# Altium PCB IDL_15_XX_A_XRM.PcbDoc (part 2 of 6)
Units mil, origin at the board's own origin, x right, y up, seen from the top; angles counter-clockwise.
Board outline 6653.34 x 6653.34 mil, 6 copper layers (Top Layer - SIG1, Layer 2 - GND1, Layer 3 - PWR, Layer 4 - PWR, Layer 5 - GND2, Bottom Layer - SIG4), stack 59.843 mil thick; 613 components, 324 nets, 1673 pads, 2316 vias.
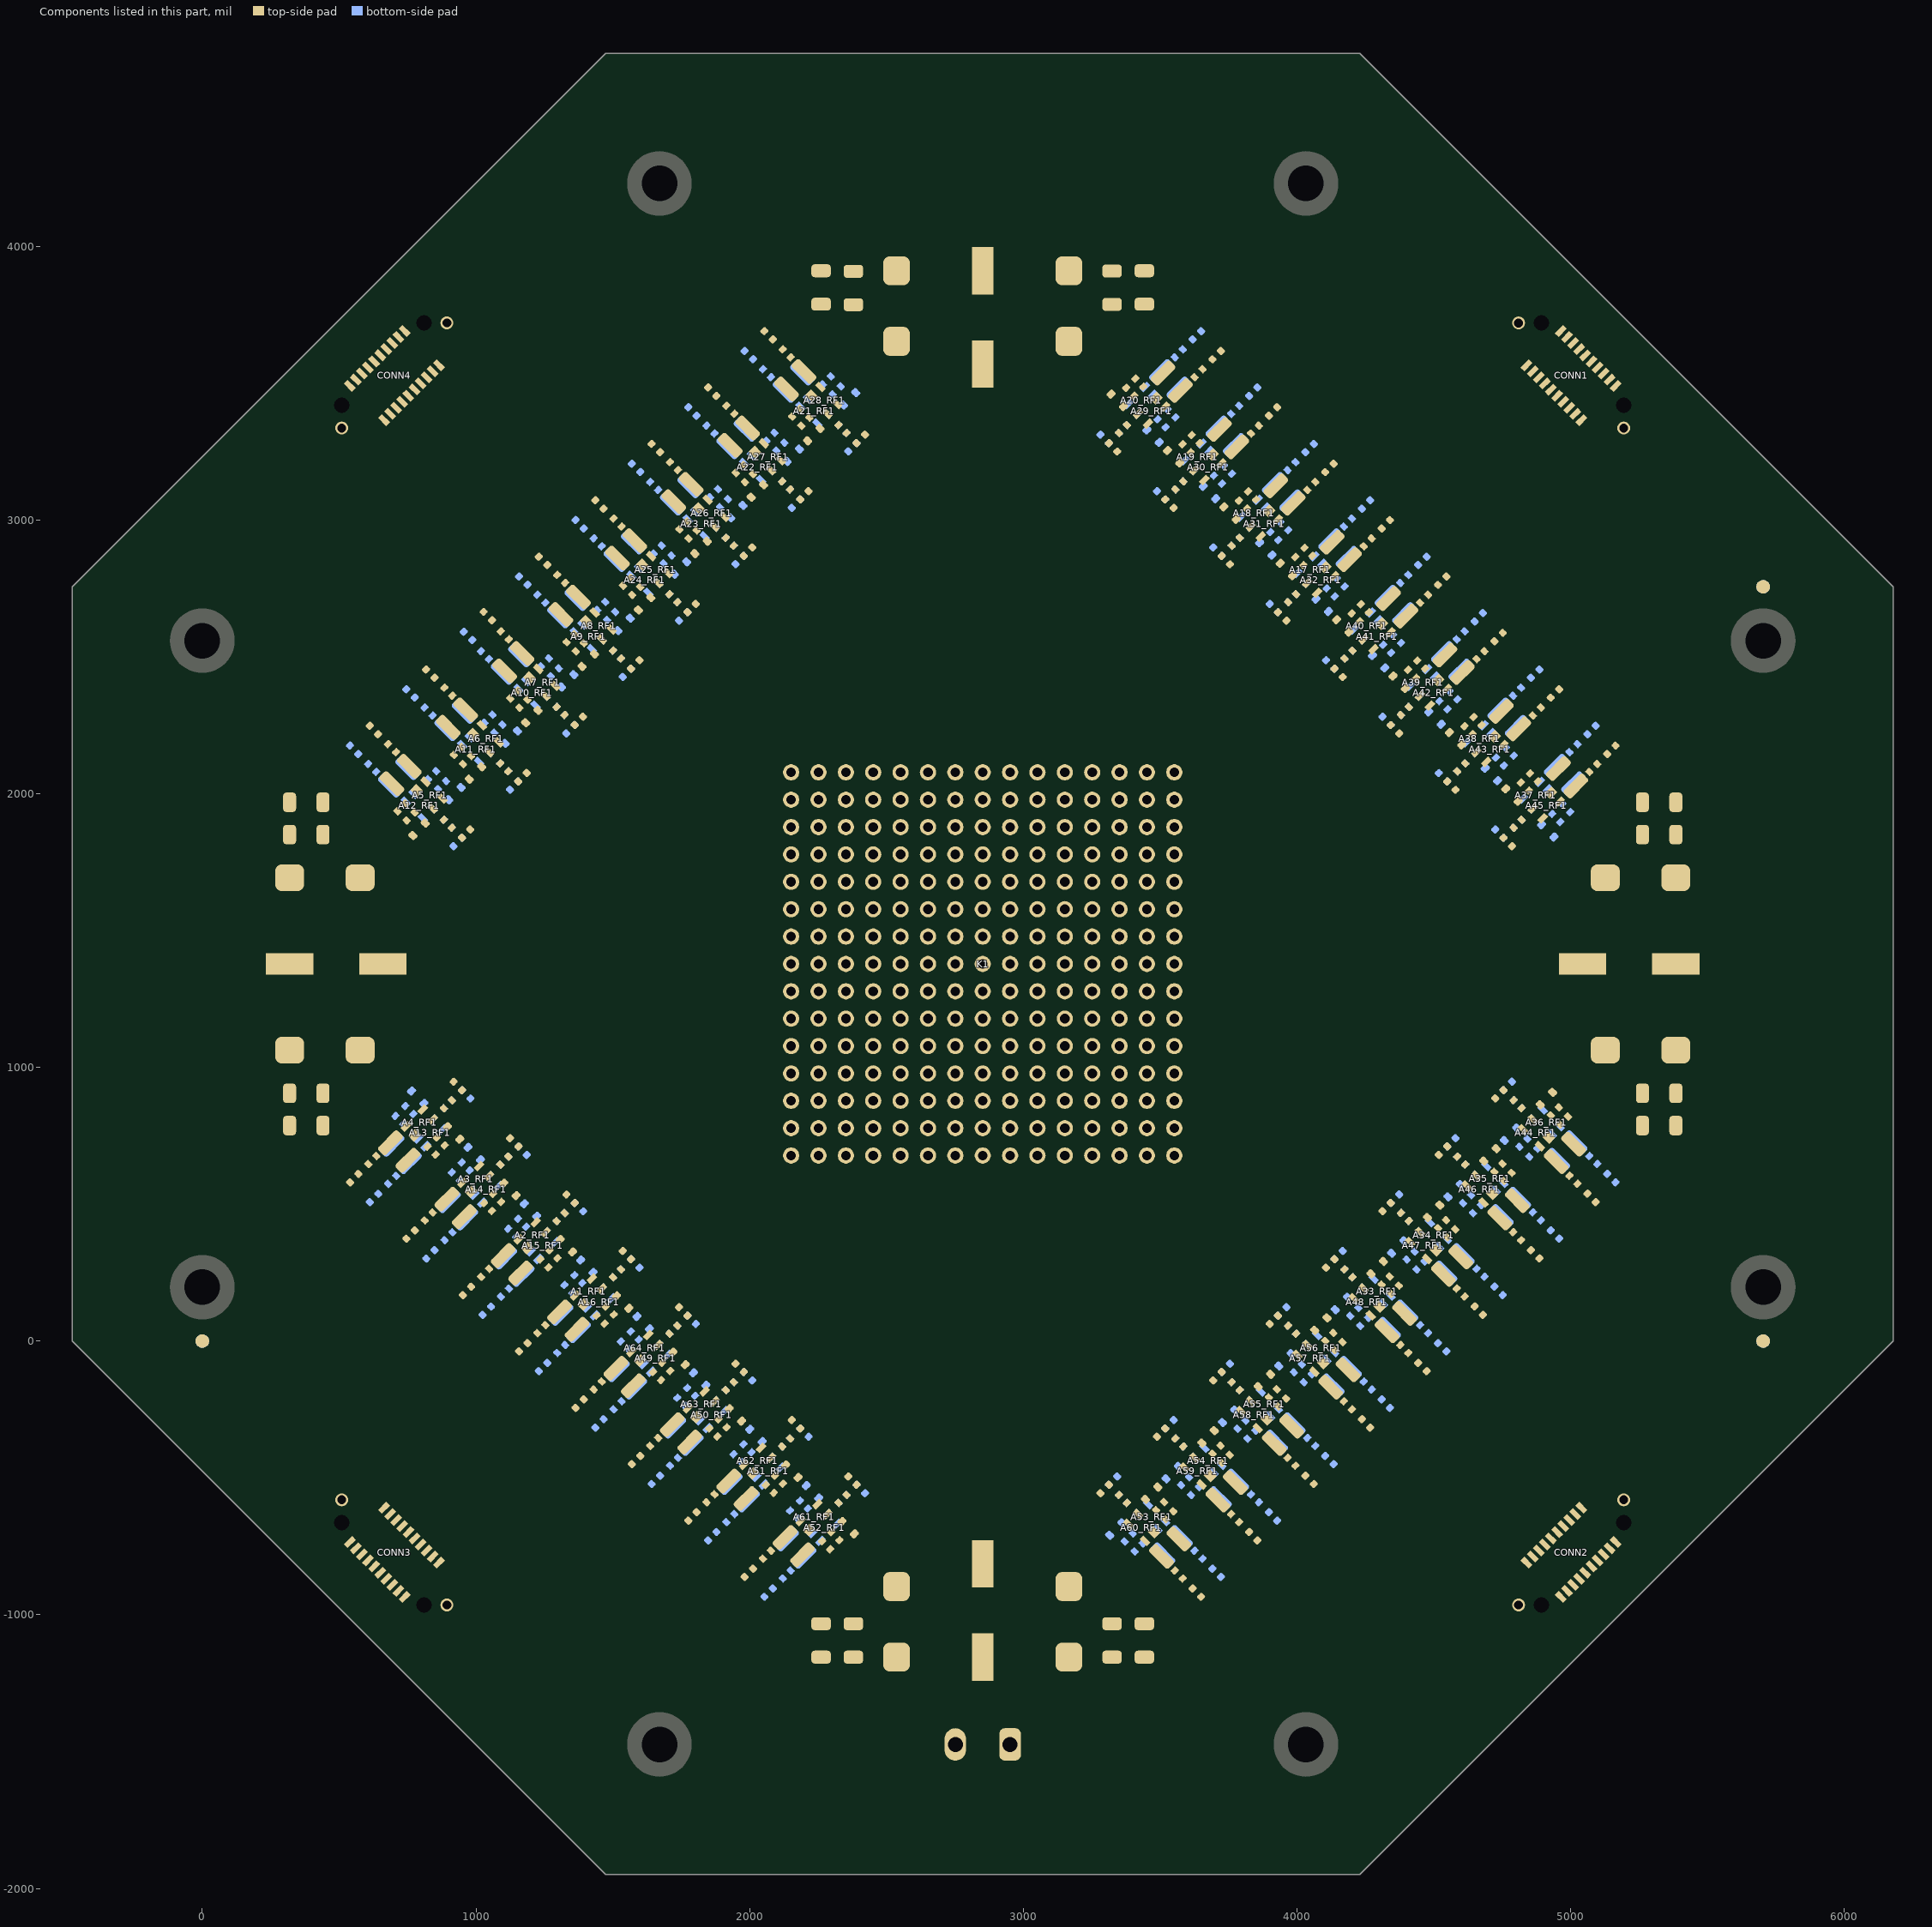
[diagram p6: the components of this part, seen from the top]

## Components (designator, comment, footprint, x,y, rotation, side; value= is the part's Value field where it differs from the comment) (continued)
A28_Cin_1 "10nF" CC0402N1R 2339.1,3332.37 r135 top (schematic designator Cin_1)
A28_L1 "1.5uH" LC1008CS 2166.5,3510.54 r225 top (schematic designator L1)
A28_L2 "0.5nH" LC0402N1R 2069.06,3674.79 r135 top (schematic designator L2)
A28_RF1 "AMP-PSA4-5043+" MMM1362 2270.7,3436.84 r225 top (schematic designator RF1)
A28_Rin_1 "390R" RC0402N1R 2405.91,3296.18 r225 top (schematic designator Rin_1)
A29_C1 "10nF" CC0402N1R 3423.54,3501.52 r315 top (schematic designator C1)
A29_C2 "100nF" CC0402N1R 3390.13,3468.11 r315 top (schematic designator C2)
A29_C3 "1uF" CC0603RF1R 3343.14,3437.15 r315 top (schematic designator C3)
A29_C13 "10nF" CC0402N1R 3640.07,3536.09 r45 top (schematic designator C13)
A29_Cin_1 "10nF" CC0402N1R 3363.77,3332.17 r45 top (schematic designator Cin_1)
A29_L1 "1.5uH" LC1008CS 3541.94,3504.77 r135 top (schematic designator L1)
A29_L2 "0.5nH" LC0402N1R 3706.18,3602.21 r45 top (schematic designator L2)
A29_RF1 "AMP-PSA4-5043+" MMM1362 3468.23,3400.58 r135 top (schematic designator RF1)
A29_Rin_1 "390R" RC0402N1R 3327.58,3265.36 r135 top (schematic designator Rin_1)
A30_C1 "10nF" CC0402N1R 3629.54,3295.51 r315 top (schematic designator C1)
A30_C2 "100nF" CC0402N1R 3596.14,3262.1 r315 top (schematic designator C2)
A30_C3 "1uF" CC0603RF1R 3549.15,3231.14 r315 top (schematic designator C3)
A30_C13 "10nF" CC0402N1R 3846.07,3330.08 r45 top (schematic designator C13)
A30_Cin_1 "10nF" CC0402N1R 3569.77,3126.17 r45 top (schematic designator Cin_1)
A30_L1 "1.5uH" LC1008CS 3747.94,3298.77 r135 top (schematic designator L1)
A30_L2 "0.5nH" LC0402N1R 3912.19,3396.2 r45 top (schematic designator L2)
A30_RF1 "AMP-PSA4-5043+" MMM1362 3674.24,3194.57 r135 top (schematic designator RF1)
A30_Rin_1 "390R" RC0402N1R 3533.58,3059.35 r135 top (schematic designator Rin_1)
A31_C1 "10nF" CC0402N1R 3835.55,3089.5 r315 top (schematic designator C1)
A31_C2 "100nF" CC0402N1R 3802.14,3056.09 r315 top (schematic designator C2)
A31_C3 "1uF" CC0603RF1R 3755.16,3025.13 r315 top (schematic designator C3)
A31_C13 "10nF" CC0402N1R 4052.08,3124.08 r45 top (schematic designator C13)
A31_Cin_1 "10nF" CC0402N1R 3775.78,2920.16 r45 top (schematic designator Cin_1)
A31_L1 "1.5uH" LC1008CS 3953.95,3092.76 r135 top (schematic designator L1)
A31_L2 "0.5nH" LC0402N1R 4118.2,3190.19 r45 top (schematic designator L2)
A31_RF1 "AMP-PSA4-5043+" MMM1362 3880.25,2988.56 r135 top (schematic designator RF1)
A31_Rin_1 "390R" RC0402N1R 3739.59,2853.34 r135 top (schematic designator Rin_1)
A32_C1 "10nF" CC0402N1R 4041.56,2883.49 r315 top (schematic designator C1)
A32_C2 "100nF" CC0402N1R 4008.15,2850.09 r315 top (schematic designator C2)
A32_C3 "1uF" CC0603RF1R 3961.17,2819.12 r315 top (schematic designator C3)
A32_C13 "10nF" CC0402N1R 4258.09,2918.07 r45 top (schematic designator C13)
A32_Cin_1 "10nF" CC0402N1R 3981.79,2714.15 r45 top (schematic designator Cin_1)
A32_L1 "1.5uH" LC1008CS 4159.96,2886.75 r135 top (schematic designator L1)
A32_L2 "0.5nH" LC0402N1R 4324.21,2984.19 r45 top (schematic designator L2)
A32_RF1 "AMP-PSA4-5043+" MMM1362 4086.26,2782.56 r135 top (schematic designator RF1)
A32_Rin_1 "390R" RC0402N1R 3945.6,2647.34 r135 top (schematic designator Rin_1)
A33_C1 "10nF" CC0402N1R 4245.12,70.21 r45 bottom (schematic designator C1)
A33_C2 "100nF" CC0402N1R 4208.93,106.4 r45 bottom (schematic designator C2)
A33_C3 "1uF" CC0603RF1R 4161.96,137.38 r45 bottom (schematic designator C3)
A33_C13 "10nF" CC0402N1R 4464.13,43.68 r315 bottom (schematic designator C13)
A33_Cin_1 "10nF" CC0402N1R 4187.83,247.6 r315 bottom (schematic designator Cin_1)
A33_L1 "1.5uH" LC1008CS 4366,75 r225 bottom (schematic designator L1)
A33_L2 "0.5nH" LC0402N1R 4530.25,-22.44 r315 bottom (schematic designator L2)
A33_RF1 "AMP-PSA4-5043+" MMM1362 4292.3,179.19 r225 bottom (schematic designator RF1)
A33_Rin_1 "390R" RC0402N1R 4151.64,314.41 r225 bottom (schematic designator Rin_1)
A34_C1 "10nF" CC0402N1R 4451.13,276.22 r45 bottom (schematic designator C1)
A34_C2 "100nF" CC0402N1R 4414.94,312.41 r45 bottom (schematic designator C2)
A34_C3 "1uF" CC0603RF1R 4367.97,343.39 r45 bottom (schematic designator C3)
A34_C13 "10nF" CC0402N1R 4670.14,249.69 r315 bottom (schematic designator C13)
A34_Cin_1 "10nF" CC0402N1R 4393.84,453.61 r315 bottom (schematic designator Cin_1)
A34_L1 "1.5uH" LC1008CS 4572,281.01 r225 bottom (schematic designator L1)
A34_L2 "0.5nH" LC0402N1R 4736.25,183.57 r315 bottom (schematic designator L2)
A34_RF1 "AMP-PSA4-5043+" MMM1362 4498.3,385.2 r225 bottom (schematic designator RF1)
A34_Rin_1 "390R" RC0402N1R 4357.65,520.42 r225 bottom (schematic designator Rin_1)
A35_C1 "10nF" CC0402N1R 4657.14,482.22 r45 bottom (schematic designator C1)
A35_C2 "100nF" CC0402N1R 4620.95,518.41 r45 bottom (schematic designator C2)
A35_C3 "1uF" CC0603RF1R 4573.98,549.39 r45 bottom (schematic designator C3)
A35_C13 "10nF" CC0402N1R 4876.14,455.69 r315 bottom (schematic designator C13)
A35_Cin_1 "10nF" CC0402N1R 4599.84,659.61 r315 bottom (schematic designator Cin_1)
A35_L1 "1.5uH" LC1008CS 4778.01,487.01 r225 bottom (schematic designator L1)
A35_L2 "0.5nH" LC0402N1R 4942.26,389.58 r315 bottom (schematic designator L2)
A35_RF1 "AMP-PSA4-5043+" MMM1362 4704.31,591.21 r225 bottom (schematic designator RF1)
A35_Rin_1 "390R" RC0402N1R 4563.65,726.43 r225 bottom (schematic designator Rin_1)
A36_C1 "10nF" CC0402N1R 4863.14,688.23 r45 bottom (schematic designator C1)
A36_C2 "100nF" CC0402N1R 4826.95,724.42 r45 bottom (schematic designator C2)
A36_C3 "1uF" CC0603RF1R 4779.98,755.4 r45 bottom (schematic designator C3)
A36_C13 "10nF" CC0402N1R 5082.15,661.7 r315 bottom (schematic designator C13)
A36_Cin_1 "10nF" CC0402N1R 4805.85,865.62 r315 bottom (schematic designator Cin_1)
A36_L1 "1.5uH" LC1008CS 4984.02,693.02 r225 bottom (schematic designator L1)
A36_L2 "0.5nH" LC0402N1R 5148.27,595.58 r315 bottom (schematic designator L2)
A36_RF1 "AMP-PSA4-5043+" MMM1362 4910.32,797.22 r225 bottom (schematic designator RF1)
A36_Rin_1 "390R" RC0402N1R 4769.66,932.43 r225 bottom (schematic designator Rin_1)
A37_C1 "10nF" CC0402N1R 4983.24,1947.38 r135 bottom (schematic designator C1)
A37_C2 "100nF" CC0402N1R 4947.05,1911.19 r135 bottom (schematic designator C2)
A37_C3 "1uF" CC0603RF1R 4916.07,1864.22 r135 bottom (schematic designator C3)
A37_C13 "10nF" CC0402N1R 5009.77,2166.39 r45 bottom (schematic designator C13)
A37_Cin_1 "10nF" CC0402N1R 4805.85,1890.09 r45 bottom (schematic designator Cin_1)
A37_L1 "1.5uH" LC1008CS 4978.45,2068.25 r315 bottom (schematic designator L1)
A37_L2 "0.5nH" LC0402N1R 5075.89,2232.5 r45 bottom (schematic designator L2)
A37_RF1 "AMP-PSA4-5043+" MMM1362 4874.26,1994.55 r315 bottom (schematic designator RF1)
A37_Rin_1 "390R" RC0402N1R 4739.04,1853.9 r315 bottom (schematic designator Rin_1)
A38_C1 "10nF" CC0402N1R 4777.23,2153.39 r135 bottom (schematic designator C1)
A38_C2 "100nF" CC0402N1R 4741.04,2117.2 r135 bottom (schematic designator C2)
A38_C3 "1uF" CC0603RF1R 4710.06,2070.23 r135 bottom (schematic designator C3)
A38_C13 "10nF" CC0402N1R 4803.76,2372.39 r45 bottom (schematic designator C13)
A38_Cin_1 "10nF" CC0402N1R 4599.84,2096.09 r45 bottom (schematic designator Cin_1)
A38_L1 "1.5uH" LC1008CS 4772.45,2274.26 r315 bottom (schematic designator L1)
A38_L2 "0.5nH" LC0402N1R 4869.88,2438.51 r45 bottom (schematic designator L2)
A38_RF1 "AMP-PSA4-5043+" MMM1362 4668.25,2200.56 r315 bottom (schematic designator RF1)
A38_Rin_1 "390R" RC0402N1R 4533.03,2059.9 r315 bottom (schematic designator Rin_1)
A39_C1 "10nF" CC0402N1R 4571.23,2359.39 r135 bottom (schematic designator C1)
A39_C2 "100nF" CC0402N1R 4535.04,2323.2 r135 bottom (schematic designator C2)
A39_C3 "1uF" CC0603RF1R 4504.06,2276.23 r135 bottom (schematic designator C3)
A39_C13 "10nF" CC0402N1R 4597.76,2578.4 r45 bottom (schematic designator C13)
A39_Cin_1 "10nF" CC0402N1R 4393.84,2302.1 r45 bottom (schematic designator Cin_1)
A39_L1 "1.5uH" LC1008CS 4566.44,2480.27 r315 bottom (schematic designator L1)
A39_L2 "0.5nH" LC0402N1R 4663.87,2644.52 r45 bottom (schematic designator L2)
A39_RF1 "AMP-PSA4-5043+" MMM1362 4462.24,2406.57 r315 bottom (schematic designator RF1)
A39_Rin_1 "390R" RC0402N1R 4327.02,2265.91 r315 bottom (schematic designator Rin_1)
A40_C1 "10nF" CC0402N1R 4365.22,2565.4 r135 bottom (schematic designator C1)
A40_C2 "100nF" CC0402N1R 4329.03,2529.21 r135 bottom (schematic designator C2)
A40_C3 "1uF" CC0603RF1R 4298.05,2482.24 r135 bottom (schematic designator C3)
A40_C13 "10nF" CC0402N1R 4391.75,2784.41 r45 bottom (schematic designator C13)
A40_Cin_1 "10nF" CC0402N1R 4187.83,2508.11 r45 bottom (schematic designator Cin_1)
A40_L1 "1.5uH" LC1008CS 4360.43,2686.28 r315 bottom (schematic designator L1)
A40_L2 "0.5nH" LC0402N1R 4457.87,2850.53 r45 bottom (schematic designator L2)
A40_RF1 "AMP-PSA4-5043+" MMM1362 4256.24,2612.58 r315 bottom (schematic designator RF1)
A40_Rin_1 "390R" RC0402N1R 4121.02,2471.92 r315 bottom (schematic designator Rin_1)
A41_C1 "10nF" CC0402N1R 4247.6,2677.45 r315 top (schematic designator C1)
A41_C2 "100nF" CC0402N1R 4214.19,2644.05 r315 top (schematic designator C2)
A41_C3 "1uF" CC0603RF1R 4167.21,2613.08 r315 top (schematic designator C3)
A41_C13 "10nF" CC0402N1R 4464.13,2712.03 r45 top (schematic designator C13)
A41_Cin_1 "10nF" CC0402N1R 4187.83,2508.11 r45 top (schematic designator Cin_1)
A41_L1 "1.5uH" LC1008CS 4366,2680.71 r135 top (schematic designator L1)
A41_L2 "0.5nH" LC0402N1R 4530.25,2778.15 r45 top (schematic designator L2)
A41_RF1 "AMP-PSA4-5043+" MMM1362 4292.3,2576.51 r135 top (schematic designator RF1)
A41_Rin_1 "390R" RC0402N1R 4151.64,2441.3 r135 top (schematic designator Rin_1)
A42_C1 "10nF" CC0402N1R 4453.61,2471.45 r315 top (schematic designator C1)
A42_C2 "100nF" CC0402N1R 4420.2,2438.04 r315 top (schematic designator C2)
A42_C3 "1uF" CC0603RF1R 4373.21,2407.08 r315 top (schematic designator C3)
A42_C13 "10nF" CC0402N1R 4670.14,2506.02 r45 top (schematic designator C13)
A42_Cin_1 "10nF" CC0402N1R 4393.84,2302.1 r45 top (schematic designator Cin_1)
A42_L1 "1.5uH" LC1008CS 4572.01,2474.7 r135 top (schematic designator L1)
A42_L2 "0.5nH" LC0402N1R 4736.25,2572.14 r45 top (schematic designator L2)
A42_RF1 "AMP-PSA4-5043+" MMM1362 4498.31,2370.51 r135 top (schematic designator RF1)
A42_Rin_1 "390R" RC0402N1R 4357.65,2235.29 r135 top (schematic designator Rin_1)
A43_C1 "10nF" CC0402N1R 4659.61,2265.44 r315 top (schematic designator C1)
A43_C2 "100nF" CC0402N1R 4626.21,2232.03 r315 top (schematic designator C2)
A43_C3 "1uF" CC0603RF1R 4579.22,2201.07 r315 top (schematic designator C3)
A43_C13 "10nF" CC0402N1R 4876.15,2300.01 r45 top (schematic designator C13)
A43_Cin_1 "10nF" CC0402N1R 4599.84,2096.09 r45 top (schematic designator Cin_1)
A43_L1 "1.5uH" LC1008CS 4778.01,2268.69 r135 top (schematic designator L1)
A43_L2 "0.5nH" LC0402N1R 4942.26,2366.13 r45 top (schematic designator L2)
A43_RF1 "AMP-PSA4-5043+" MMM1362 4704.31,2164.5 r135 top (schematic designator RF1)
A43_Rin_1 "390R" RC0402N1R 4563.65,2029.28 r135 top (schematic designator Rin_1)
A44_C1 "10nF" CC0402N1R 4975.2,805.85 r225 top (schematic designator C1)
A44_C2 "100nF" CC0402N1R 4941.79,839.26 r225 top (schematic designator C2)
A44_C3 "1uF" CC0603RF1R 4910.83,886.24 r225 top (schematic designator C3)
A44_C13 "10nF" CC0402N1R 5009.77,589.32 r315 top (schematic designator C13)
A44_Cin_1 "10nF" CC0402N1R 4805.85,865.62 r315 top (schematic designator Cin_1)
A44_L1 "1.5uH" LC1008CS 4978.45,687.45 r45 top (schematic designator L1)
A44_L2 "0.5nH" LC0402N1R 5075.89,523.2 r315 top (schematic designator L2)
A44_RF1 "AMP-PSA4-5043+" MMM1362 4874.26,761.15 r45 top (schematic designator RF1)
A44_Rin_1 "390R" RC0402N1R 4739.04,901.81 r45 top (schematic designator Rin_1)
A45_C1 "10nF" CC0402N1R 4865.62,2059.43 r315 top (schematic designator C1)
A45_C2 "100nF" CC0402N1R 4832.22,2026.02 r315 top (schematic designator C2)
A45_C3 "1uF" CC0603RF1R 4785.23,1995.06 r315 top (schematic designator C3)
A45_C13 "10nF" CC0402N1R 5082.15,2094.01 r45 top (schematic designator C13)
A45_Cin_1 "10nF" CC0402N1R 4805.85,1890.09 r45 top (schematic designator Cin_1)
A45_L1 "1.5uH" LC1008CS 4986.8,2059.9 r135 top (schematic designator L1)
A45_L2 "0.5nH" LC0402N1R 5148.27,2160.12 r45 top (schematic designator L2)
A45_RF1 "AMP-PSA4-5043+" MMM1362 4910.32,1958.49 r135 top (schematic designator RF1)
A45_Rin_1 "390R" RC0402N1R 4769.66,1823.27 r135 top (schematic designator Rin_1)
A46_C1 "10nF" CC0402N1R 4769.19,599.84 r225 top (schematic designator C1)
A46_C2 "100nF" CC0402N1R 4735.78,633.25 r225 top (schematic designator C2)
A46_C3 "1uF" CC0603RF1R 4704.82,680.24 r225 top (schematic designator C3)
A46_C13 "10nF" CC0402N1R 4803.76,383.31 r315 top (schematic designator C13)
A46_Cin_1 "10nF" CC0402N1R 4599.84,659.61 r315 top (schematic designator Cin_1)
A46_L1 "1.5uH" LC1008CS 4772.44,481.44 r45 top (schematic designator L1)
A46_L2 "0.5nH" LC0402N1R 4869.88,317.2 r315 top (schematic designator L2)
A46_RF1 "AMP-PSA4-5043+" MMM1362 4668.25,555.15 r45 top (schematic designator RF1)
A46_Rin_1 "390R" RC0402N1R 4533.03,695.8 r45 top (schematic designator Rin_1)
A47_C1 "10nF" CC0402N1R 4563.18,393.84 r225 top (schematic designator C1)
A47_C2 "100nF" CC0402N1R 4529.77,427.24 r225 top (schematic designator C2)
A47_C3 "1uF" CC0603RF1R 4498.81,474.23 r225 top (schematic designator C3)
A47_C13 "10nF" CC0402N1R 4597.76,177.31 r315 top (schematic designator C13)
A47_Cin_1 "10nF" CC0402N1R 4393.84,453.61 r315 top (schematic designator Cin_1)
A47_L1 "1.5uH" LC1008CS 4566.44,275.44 r45 top (schematic designator L1)
A47_L2 "0.5nH" LC0402N1R 4663.87,111.19 r315 top (schematic designator L2)
A47_RF1 "AMP-PSA4-5043+" MMM1362 4462.24,349.14 r45 top (schematic designator RF1)
A47_Rin_1 "390R" RC0402N1R 4327.02,489.8 r45 top (schematic designator Rin_1)
A48_C1 "10nF" CC0402N1R 4357.17,187.83 r225 top (schematic designator C1)
A48_C2 "100nF" CC0402N1R 4323.77,221.23 r225 top (schematic designator C2)
A48_C3 "1uF" CC0603RF1R 4292.8,268.22 r225 top (schematic designator C3)
A48_C13 "10nF" CC0402N1R 4391.75,-28.7 r315 top (schematic designator C13)
A48_Cin_1 "10nF" CC0402N1R 4187.83,247.6 r315 top (schematic designator Cin_1)
A48_L1 "1.5uH" LC1008CS 4360.43,69.43 r45 top (schematic designator L1)
A48_L2 "0.5nH" LC0402N1R 4457.87,-94.82 r315 top (schematic designator L2)
A48_RF1 "AMP-PSA4-5043+" MMM1362 4256.23,143.13 r45 top (schematic designator RF1)
A48_Rin_1 "390R" RC0402N1R 4121.02,283.79 r45 top (schematic designator Rin_1)
A49_C1 "10nF" CC0402N1R 1543.78,-15.74 r315 bottom (schematic designator C1)
A49_C2 "100nF" CC0402N1R 1579.97,20.46 r315 bottom (schematic designator C2)
A49_C3 "1uF" CC0603RF1R 1610.95,67.42 r315 bottom (schematic designator C3)
A49_C13 "10nF" CC0402N1R 1517.25,-234.74 r225 bottom (schematic designator C13)
A49_Cin_1 "10nF" CC0402N1R 1721.17,41.56 r225 bottom (schematic designator Cin_1)
A49_L1 "1.5uH" LC1008CS 1548.57,-136.61 r135 bottom (schematic designator L1)
A49_L2 "0.5nH" LC0402N1R 1451.14,-300.86 r225 bottom (schematic designator L2)
A49_RF1 "AMP-PSA4-5043+" MMM1362 1652.77,-62.91 r135 bottom (schematic designator RF1)
A49_Rin_1 "390R" RC0402N1R 1787.99,77.75 r135 bottom (schematic designator Rin_1)
A50_C1 "10nF" CC0402N1R 1749.82,-221.78 r315 bottom (schematic designator C1)
A50_C2 "100nF" CC0402N1R 1786.01,-185.59 r315 bottom (schematic designator C2)
A50_C3 "1uF" CC0603RF1R 1816.99,-138.62 r315 bottom (schematic designator C3)
A50_C13 "10nF" CC0402N1R 1723.29,-440.78 r225 bottom (schematic designator C13)
A50_Cin_1 "10nF" CC0402N1R 1927.21,-164.48 r225 bottom (schematic designator Cin_1)
A50_L1 "1.5uH" LC1008CS 1754.61,-342.65 r135 bottom (schematic designator L1)
A50_L2 "0.5nH" LC0402N1R 1657.18,-506.9 r225 bottom (schematic designator L2)
A50_RF1 "AMP-PSA4-5043+" MMM1362 1858.81,-268.95 r135 bottom (schematic designator RF1)
A50_Rin_1 "390R" RC0402N1R 1994.03,-128.29 r135 bottom (schematic designator Rin_1)
A51_C1 "10nF" CC0402N1R 1955.83,-427.78 r315 bottom (schematic designator C1)
A51_C2 "100nF" CC0402N1R 1992.02,-391.59 r315 bottom (schematic designator C2)
A51_C3 "1uF" CC0603RF1R 2023,-344.62 r315 bottom (schematic designator C3)
A51_C13 "10nF" CC0402N1R 1929.3,-646.79 r225 bottom (schematic designator C13)
A51_Cin_1 "10nF" CC0402N1R 2133.22,-370.49 r225 bottom (schematic designator Cin_1)
A51_L1 "1.5uH" LC1008CS 1960.62,-548.66 r135 bottom (schematic designator L1)
A51_L2 "0.5nH" LC0402N1R 1863.18,-712.91 r225 bottom (schematic designator L2)
A51_RF1 "AMP-PSA4-5043+" MMM1362 2064.81,-474.96 r135 bottom (schematic designator RF1)
A51_Rin_1 "390R" RC0402N1R 2200.03,-334.3 r135 bottom (schematic designator Rin_1)
A52_C1 "10nF" CC0402N1R 2161.84,-633.79 r315 bottom (schematic designator C1)
A52_C2 "100nF" CC0402N1R 2198.03,-597.6 r315 bottom (schematic designator C2)
A52_C3 "1uF" CC0603RF1R 2229.01,-550.63 r315 bottom (schematic designator C3)
A52_C13 "10nF" CC0402N1R 2135.31,-852.8 r225 bottom (schematic designator C13)
A52_Cin_1 "10nF" CC0402N1R 2339.23,-576.5 r225 bottom (schematic designator Cin_1)
A52_L1 "1.5uH" LC1008CS 2166.63,-754.67 r135 bottom (schematic designator L1)
A52_L2 "0.5nH" LC0402N1R 2069.19,-918.92 r225 bottom (schematic designator L2)
A52_RF1 "AMP-PSA4-5043+" MMM1362 2270.82,-680.97 r135 bottom (schematic designator RF1)
A52_Rin_1 "390R" RC0402N1R 2406.04,-540.31 r135 bottom (schematic designator Rin_1)
A53_C1 "10nF" CC0402N1R 3421.02,-753.89 r45 bottom (schematic designator C1)
A53_C2 "100nF" CC0402N1R 3384.83,-717.7 r45 bottom (schematic designator C2)
A53_C3 "1uF" CC0603RF1R 3337.86,-686.72 r45 bottom (schematic designator C3)
A53_C13 "10nF" CC0402N1R 3640.03,-780.42 r315 bottom (schematic designator C13)
A53_Cin_1 "10nF" CC0402N1R 3363.73,-576.5 r315 bottom (schematic designator Cin_1)
A53_L1 "1.5uH" LC1008CS 3541.9,-749.1 r225 bottom (schematic designator L1)
A53_L2 "0.5nH" LC0402N1R 3706.15,-846.54 r315 bottom (schematic designator L2)
A53_RF1 "AMP-PSA4-5043+" MMM1362 3468.2,-644.9 r225 bottom (schematic designator RF1)
A53_Rin_1 "390R" RC0402N1R 3327.54,-509.69 r225 bottom (schematic designator Rin_1)
A54_C1 "10nF" CC0402N1R 3627.03,-547.88 r45 bottom (schematic designator C1)
A54_C2 "100nF" CC0402N1R 3590.84,-511.69 r45 bottom (schematic designator C2)
A54_C3 "1uF" CC0603RF1R 3543.87,-480.71 r45 bottom (schematic designator C3)
A54_C13 "10nF" CC0402N1R 3846.04,-574.41 r315 bottom (schematic designator C13)
A54_Cin_1 "10nF" CC0402N1R 3569.74,-370.49 r315 bottom (schematic designator Cin_1)
A54_L1 "1.5uH" LC1008CS 3747.91,-543.09 r225 bottom (schematic designator L1)
A54_L2 "0.5nH" LC0402N1R 3912.16,-640.53 r315 bottom (schematic designator L2)
A54_RF1 "AMP-PSA4-5043+" MMM1362 3674.21,-438.9 r225 bottom (schematic designator RF1)
A54_Rin_1 "390R" RC0402N1R 3533.55,-303.68 r225 bottom (schematic designator Rin_1)
A55_C1 "10nF" CC0402N1R 3833.04,-341.87 r45 bottom (schematic designator C1)
A55_C2 "100nF" CC0402N1R 3796.85,-305.68 r45 bottom (schematic designator C2)
A55_C3 "1uF" CC0603RF1R 3749.88,-274.7 r45 bottom (schematic designator C3)
A55_C13 "10nF" CC0402N1R 4052.05,-368.4 r315 bottom (schematic designator C13)
A55_Cin_1 "10nF" CC0402N1R 3775.75,-164.48 r315 bottom (schematic designator Cin_1)
A55_L1 "1.5uH" LC1008CS 3953.92,-337.08 r225 bottom (schematic designator L1)
A55_L2 "0.5nH" LC0402N1R 4118.16,-434.52 r315 bottom (schematic designator L2)
A55_RF1 "AMP-PSA4-5043+" MMM1362 3880.21,-232.89 r225 bottom (schematic designator RF1)
A55_Rin_1 "390R" RC0402N1R 3739.56,-97.67 r225 bottom (schematic designator Rin_1)
A56_C1 "10nF" CC0402N1R 4039.08,-135.83 r45 bottom (schematic designator C1)
A56_C2 "100nF" CC0402N1R 4002.89,-99.64 r45 bottom (schematic designator C2)
A56_C3 "1uF" CC0603RF1R 3955.92,-68.66 r45 bottom (schematic designator C3)
A56_C13 "10nF" CC0402N1R 4258.09,-162.36 r315 bottom (schematic designator C13)
A56_Cin_1 "10nF" CC0402N1R 3981.79,41.56 r315 bottom (schematic designator Cin_1)
A56_L1 "1.5uH" LC1008CS 4159.96,-131.04 r225 bottom (schematic designator L1)
A56_L2 "0.5nH" LC0402N1R 4324.21,-228.48 r315 bottom (schematic designator L2)
A56_RF1 "AMP-PSA4-5043+" MMM1362 4086.26,-26.85 r225 bottom (schematic designator RF1)
A56_Rin_1 "390R" RC0402N1R 3945.6,108.37 r225 bottom (schematic designator Rin_1)
A57_C1 "10nF" CC0402N1R 4151.13,-18.21 r225 top (schematic designator C1)
A57_C2 "100nF" CC0402N1R 4117.72,15.19 r225 top (schematic designator C2)
A57_C3 "1uF" CC0603RF1R 4086.76,62.18 r225 top (schematic designator C3)
A57_C13 "10nF" CC0402N1R 4185.71,-234.74 r315 top (schematic designator C13)
A57_Cin_1 "10nF" CC0402N1R 3981.79,41.56 r315 top (schematic designator Cin_1)
A57_L1 "1.5uH" LC1008CS 4154.39,-136.61 r45 top (schematic designator L1)
A57_L2 "0.5nH" LC0402N1R 4251.82,-300.86 r315 top (schematic designator L2)
A57_RF1 "AMP-PSA4-5043+" MMM1362 4050.19,-62.91 r45 top (schematic designator RF1)
A57_Rin_1 "390R" RC0402N1R 3914.97,77.75 r45 top (schematic designator Rin_1)
A58_C1 "10nF" CC0402N1R 3945.09,-224.25 r225 top (schematic designator C1)
A58_C2 "100nF" CC0402N1R 3911.68,-190.85 r225 top (schematic designator C2)
A58_C3 "1uF" CC0603RF1R 3880.72,-143.86 r225 top (schematic designator C3)
A58_C13 "10nF" CC0402N1R 3979.67,-440.78 r315 top (schematic designator C13)
A58_Cin_1 "10nF" CC0402N1R 3775.75,-164.48 r315 top (schematic designator Cin_1)
A58_L1 "1.5uH" LC1008CS 3948.35,-342.65 r45 top (schematic designator L1)
A58_L2 "0.5nH" LC0402N1R 4045.78,-506.9 r315 top (schematic designator L2)
A58_RF1 "AMP-PSA4-5043+" MMM1362 3844.15,-268.95 r45 top (schematic designator RF1)
A58_Rin_1 "390R" RC0402N1R 3708.93,-128.29 r45 top (schematic designator Rin_1)
A59_C1 "10nF" CC0402N1R 3739.08,-430.26 r225 top (schematic designator C1)
A59_C2 "100nF" CC0402N1R 3705.68,-396.85 r225 top (schematic designator C2)
A59_C3 "1uF" CC0603RF1R 3674.71,-349.87 r225 top (schematic designator C3)
A59_C13 "10nF" CC0402N1R 3773.66,-646.79 r315 top (schematic designator C13)
A59_Cin_1 "10nF" CC0402N1R 3569.74,-370.49 r315 top (schematic designator Cin_1)
A59_L1 "1.5uH" LC1008CS 3742.34,-548.66 r45 top (schematic designator L1)
A59_L2 "0.5nH" LC0402N1R 3839.78,-712.91 r315 top (schematic designator L2)
A59_RF1 "AMP-PSA4-5043+" MMM1362 3638.14,-474.96 r45 top (schematic designator RF1)
A59_Rin_1 "390R" RC0402N1R 3502.93,-334.3 r45 top (schematic designator Rin_1)
A60_C1 "10nF" CC0402N1R 3533.08,-636.27 r225 top (schematic designator C1)
A60_C2 "100nF" CC0402N1R 3499.67,-602.86 r225 top (schematic designator C2)
A60_C3 "1uF" CC0603RF1R 3468.71,-555.88 r225 top (schematic designator C3)
A60_C13 "10nF" CC0402N1R 3567.65,-852.8 r315 top (schematic designator C13)
A60_Cin_1 "10nF" CC0402N1R 3363.73,-576.5 r315 top (schematic designator Cin_1)
A60_L1 "1.5uH" LC1008CS 3536.33,-754.67 r45 top (schematic designator L1)
A60_L2 "0.5nH" LC0402N1R 3633.77,-918.92 r315 top (schematic designator L2)
A60_RF1 "AMP-PSA4-5043+" MMM1362 3432.14,-680.97 r45 top (schematic designator RF1)
A60_Rin_1 "390R" RC0402N1R 3296.92,-540.31 r45 top (schematic designator Rin_1)
A61_C1 "10nF" CC0402N1R 2279.46,-745.84 r135 top (schematic designator C1)
A61_C2 "100nF" CC0402N1R 2312.86,-712.44 r135 top (schematic designator C2)
A61_C3 "1uF" CC0603RF1R 2359.85,-681.47 r135 top (schematic designator C3)
A61_C13 "10nF" CC0402N1R 2062.93,-780.42 r225 top (schematic designator C13)
A61_Cin_1 "10nF" CC0402N1R 2339.23,-576.5 r225 top (schematic designator Cin_1)
A61_L1 "1.5uH" LC1008CS 2161.06,-749.1 r315 top (schematic designator L1)
A61_L2 "0.5nH" LC0402N1R 1996.81,-846.54 r225 top (schematic designator L2)
A61_RF1 "AMP-PSA4-5043+" MMM1362 2234.76,-644.91 r315 top (schematic designator RF1)
A61_Rin_1 "390R" RC0402N1R 2375.42,-509.69 r315 top (schematic designator Rin_1)
A62_C1 "10nF" CC0402N1R 2073.45,-539.84 r135 top (schematic designator C1)
A62_C2 "100nF" CC0402N1R 2106.86,-506.43 r135 top (schematic designator C2)
A62_C3 "1uF" CC0603RF1R 2153.84,-475.47 r135 top (schematic designator C3)
A62_C13 "10nF" CC0402N1R 1856.92,-574.41 r225 top (schematic designator C13)
A62_Cin_1 "10nF" CC0402N1R 2133.22,-370.49 r225 top (schematic designator Cin_1)
A62_L1 "1.5uH" LC1008CS 1955.05,-543.09 r315 top (schematic designator L1)
A62_L2 "0.5nH" LC0402N1R 1790.8,-640.53 r225 top (schematic designator L2)
A62_RF1 "AMP-PSA4-5043+" MMM1362 2028.75,-438.9 r315 top (schematic designator RF1)
A62_Rin_1 "390R" RC0402N1R 2169.41,-303.68 r315 top (schematic designator Rin_1)
A63_C1 "10nF" CC0402N1R 1867.44,-333.83 r135 top (schematic designator C1)
A63_C2 "100nF" CC0402N1R 1900.85,-300.42 r135 top (schematic designator C2)
A63_C3 "1uF" CC0603RF1R 1947.84,-269.46 r135 top (schematic designator C3)
A63_C13 "10nF" CC0402N1R 1650.91,-368.4 r225 top (schematic designator C13)
A63_Cin_1 "10nF" CC0402N1R 1927.21,-164.48 r225 top (schematic designator Cin_1)
A63_L1 "1.5uH" LC1008CS 1749.04,-337.08 r315 top (schematic designator L1)
A63_L2 "0.5nH" LC0402N1R 1584.8,-434.52 r225 top (schematic designator L2)
A63_RF1 "AMP-PSA4-5043+" MMM1362 1822.74,-232.89 r315 top (schematic designator RF1)
A63_Rin_1 "390R" RC0402N1R 1963.4,-97.67 r315 top (schematic designator Rin_1)
A64_C1 "10nF" CC0402N1R 1661.4,-127.79 r135 top (schematic designator C1)
A64_C2 "100nF" CC0402N1R 1694.81,-94.38 r135 top (schematic designator C2)
A64_C3 "1uF" CC0603RF1R 1741.8,-63.42 r135 top (schematic designator C3)
A64_C13 "10nF" CC0402N1R 1444.87,-162.36 r225 top (schematic designator C13)
A64_Cin_1 "10nF" CC0402N1R 1721.17,41.56 r225 top (schematic designator Cin_1)
A64_L1 "1.5uH" LC1008CS 1543,-131.04 r315 top (schematic designator L1)
A64_L2 "0.5nH" LC0402N1R 1378.75,-228.48 r225 top (schematic designator L2)
A64_RF1 "AMP-PSA4-5043+" MMM1362 1616.7,-26.85 r315 top (schematic designator RF1)
A64_Rin_1 "390R" RC0402N1R 1757.36,108.37 r315 top (schematic designator Rin_1)
C4 "47uF" CC1206N1R 5322.89,787.4 r0 top
C5 "47uF" CC1206N1R 5322.89,905.51 r0 top
C6 "47uF" CC1206N1R 5322.89,1850.39 r0 top
C7 "47uF" CC1206N1R 5322.89,1968.5 r0 top
C8 "47uF" CC1206N1R 3441.98,3849.41 r90 top
C9 "47uF" CC1206N1R 3323.87,3848.43 r90 top
C10 "47uF" CC1206N1R 2378.99,3847.44 r90 top
C11 "47uF" CC1206N1R 2260.88,3849.41 r90 top
C12 "47uF" CC1206N1R 379.98,1850.39 r180 top
C14 "47uF" CC1206N1R 379.98,787.4 r180 top
C15 "47uF" CC1206N1R 379.98,905.51 r180 top
C16 "47uF" CC1206N1R 379.98,1968.5 r180 top
C17 "47uF" CC1206N1R 3441.98,-1093.5 r270 top
C18 "47uF" CC1206N1R 3323.87,-1093.5 r270 top
C19 "47uF" CC1206N1R 2378.99,-1093.5 r270 top
C20 "47uF" CC1206N1R 2260.88,-1093.5 r270 top
C21 "330uF" CTC-D7343-43 3166.39,3781.5 r90 top
C22 "330uF" CTC-D7343-43 2536.47,3781.5 r90 top
C23 "330uF" CTC-D7343-43 5254.98,1062.99 r0 top
C24 "330uF" CTC-D7343-43 5254.98,1692.91 r0 top
C25 "330uF" CTC-D7343-43 3166.39,-1025.59 r270 top
C26 "330uF" CTC-D7343-43 2536.47,-1025.59 r270 top
C27 "330uF" CTC-D7343-43 447.89,1692.91 r180 top
C28 "330uF" CTC-D7343-43 447.89,1062.99 r180 top
C29 "1000uF" CAPPS-D10X12.6 2851.43,3740.16 r90 top
C30 "1000uF" CAPPS-D10X12.6 5213.64,1377.95 r0 top
C31 "1000uF" CAPPS-D10X12.6 2851.43,-984.25 r270 top
C32 "1000uF" CAPPS-D10X12.6 489.23,1377.95 r180 top
CONN1 "20 pin connector" 20-pin-connector 5001.44,3527.76 r135 top
CONN2 "20 pin connector" 20-pin-connector 5001.44,-772.05 r45 top
CONN3 "20 pin connector" 20-pin-connector 701.53,-772.05 r315 top
CONN4 "20 pin connector" 20-pin-connector 701.43,3527.95 r225 top
FID1 "PCB-FIDRTB" FIDRTB50 0,0 r90 top net-tie
FID2 "PCB-FIDRTB" FIDRTB50 5702.87,0 r90 top net-tie
FID3 "PCB-FIDRTB" FIDRTB50 5702.87,2755.91 r90 top net-tie
K1 "Fermionics Socket" "Fermionics Socket 225v2" 2851.43,1377.95 r0 top
K2 "MSTBA2R5.08V" CN_PHOENIX_MSTBVA2,5/2-G-5,08 2851.43,-1473.48 r180 top

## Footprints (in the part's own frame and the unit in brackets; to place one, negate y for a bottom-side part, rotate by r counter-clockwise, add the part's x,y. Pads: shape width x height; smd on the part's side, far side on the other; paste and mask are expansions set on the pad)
20-pin-connector [mm] "ERF8-010-05.0-L-DV-L-TR"
  round 1.2 hole 0.83: 0(-6.9,0) 0(6.9,0)
  round 0 hole 1.45 unplated: 0(-5.4,-1.5) 0(5.4,-1.5)
  rect 0.5x1.1 smd: 1(3.6,2.25) 2(3.6,-2.25) 3(2.8,2.25) 4(2.8,-2.25) 5(2,2.25) 6(2,-2.25) 7(1.2,2.25) 8(1.2,-2.25) 9(0.4,2.25) 10(0.4,-2.25) 11(-0.4,2.25) 12(-0.4,-2.25) 13(-1.2,2.25) 14(-1.2,-2.25) 15(-2,2.25) 16(-2,-2.25) 17(-2.8,2.25) 18(-2.8,-2.25) 19(-3.6,2.25) 20(-3.6,-2.25)
  body extent -7.75,-2.8 7.75,2.8, height 5.11
CAPPS-D10X12.6 [mm] "Capacitor polarised SMD D10; 10.2x10.2x12.6mm"
  rect 4.4x2 smd: 1(-4.325,0) 2(4.325,0)
  silkscreen extent -6.5,-5.2 5.2,5.2, body extent -5.1,-5.1 5.1,5.1, height 12.65
CC0402N1R [mm] "Chip capacitor 0402 ROUND pad"
  rrect30% 0.55x0.65 smd mask+0.025: 1(-0.525,0) 2(0.525,0)
  silkscreen extent 0,-0.25 0,0.25, body extent -0.51,-0.25 0.51,0.25, height 0.5
CC0603RF1R [mil] "Chip capacitor 0603 RF pad ROUNDED PAD"
  rrect50% 25x30 smd: 1(-32,0) 2(32,0)
  silkscreen extent -8,-15 8,15, body extent -30,-15 30,15, height 28
CC1206N1R [mm] "Chip capacitor 1206 ROUNDED PAD"
  rrect50% 1.2x1.8 smd: 1(-1.55,0) 2(1.55,0)
  silkscreen extent -0.58,-0.76 0.58,0.76, body extent -1.6,-0.8 1.6,0.8, height 1.35
CN_PHOENIX_MSTBVA2,5/2-G-5,08 [mm] "MSTBVA2,5/2-G-5,08  2pin vertical"
  rrect50% 2x3 hole 1.4: 1(-2.54,0)
  oval 2x3 hole 1.4: 2(2.54,0)
  silkscreen extent -6.08,-3.8 6.08,4.8, body extent -6.08,-3.8 6.08,4.8, height 12.02
CTC-D7343-43 [mm] "Capacitor Tantal Chip D - 7343, H=4.3mm"
  rrect50% 2.7x2.5 smd: 1(-3.275,0) 2(3.275,0)
  silkscreen extent -4.45,-2.15 3.65,2.15, body extent -4,-2.15 4,2.15, height 4.31
"Fermionics Socket 225v2" [mm] "Fermionics Socket 225 - Rotated Pinout to match Sensor"
  round 1.5 hole 0.9: A1(17.78,-17.78) A2(17.78,-15.24) A3(17.78,-12.7) A4(17.78,-10.16) A5(17.78,-7.62) A6(17.78,-5.08) A7(17.78,-2.54) A8(17.78,0) A9(17.78,2.54) A10(17.78,5.08) A11(17.78,7.62) A12(17.78,10.16) A13(17.78,12.7) A14(17.78,15.24) A15(17.78,17.78) B1(15.24,-17.78) B2(15.24,-15.24) B3(15.24,-12.7) B4(15.24,-10.16) B5(15.24,-7.62) B6(15.24,-5.08) B7(15.24,-2.54) B8(15.24,0) B9(15.24,2.54) B10(15.24,5.08) B11(15.24,7.62) B12(15.24,10.16) B13(15.24,12.7) B14(15.24,15.24) B15(15.24,17.78) C1(12.7,-17.78) C2(12.7,-15.24) C3(12.7,-12.7) C4(12.7,-10.16) C5(12.7,-7.62) C6(12.7,-5.08) C7(12.7,-2.54) C8(12.7,0) C9(12.7,2.54) C10(12.7,5.08) C11(12.7,7.62) C12(12.7,10.16) C13(12.7,12.7) C14(12.7,15.24) C15(12.7,17.78) D1(10.16,-17.78) D2(10.16,-15.24) D3(10.16,-12.7) D4(10.16,-10.16) D5(10.16,-7.62) D6(10.16,-5.08) D7(10.16,-2.54) D8(10.16,0) D9(10.16,2.54) D10(10.16,5.08) D11(10.16,7.62) D12(10.16,10.16) D13(10.16,12.7) D14(10.16,15.24) D15(10.16,17.78) E1(7.62,-17.78) E2(7.62,-15.24) E3(7.62,-12.7) E4(7.62,-10.16) E5(7.62,-7.62) E6(7.62,-5.08) E7(7.62,-2.54) E8(7.62,0) E9(7.62,2.54) E10(7.62,5.08) E11(7.62,7.62) E12(7.62,10.16) E13(7.62,12.7) E14(7.62,15.24) E15(7.62,17.78) F1(5.08,-17.78) F2(5.08,-15.24) F3(5.08,-12.7) F4(5.08,-10.16) F5(5.08,-7.62) F6(5.08,-5.08) F7(5.08,-2.54) F8(5.08,0) F9(5.08,2.54) F10(5.08,5.08) F11(5.08,7.62) F12(5.08,10.16) F13(5.08,12.7) F14(5.08,15.24) F15(5.08,17.78) G1(2.54,-17.78) G2(2.54,-15.24) G3(2.54,-12.7) G4(2.54,-10.16) G5(2.54,-7.62) G6(2.54,-5.08) G7(2.54,-2.54) G8(2.54,0) G9(2.54,2.54) G10(2.54,5.08) G11(2.54,7.62) G12(2.54,10.16) G13(2.54,12.7) G14(2.54,15.24) G15(2.54,17.78) H1(0,-17.78) H2(0,-15.24) H3(0,-12.7) H4(0,-10.16) H5(0,-7.62) H6(0,-5.08) H7(0,-2.54) H8(0,0) H9(0,2.54) H10(0,5.08) H11(0,7.62) H12(0,10.16) H13(0,12.7) H14(0,15.24) H15(0,17.78) J1(-2.54,-17.78) J2(-2.54,-15.24) J3(-2.54,-12.7) J4(-2.54,-10.16) J5(-2.54,-7.62) J6(-2.54,-5.08) J7(-2.54,-2.54) J8(-2.54,0) J9(-2.54,2.54) J10(-2.54,5.08) J11(-2.54,7.62) J12(-2.54,10.16) J13(-2.54,12.7) J14(-2.54,15.24) J15(-2.54,17.78) K1(-5.08,-17.78) K2(-5.08,-15.24) K3(-5.08,-12.7) K4(-5.08,-10.16) K5(-5.08,-7.62) K6(-5.08,-5.08) K7(-5.08,-2.54) K8(-5.08,0) K9(-5.08,2.54) K10(-5.08,5.08) K11(-5.08,7.62) K12(-5.08,10.16) K13(-5.08,12.7) K14(-5.08,15.24) K15(-5.08,17.78) L1(-7.62,-17.78) L2(-7.62,-15.24) L3(-7.62,-12.7) L4(-7.62,-10.16) L5(-7.62,-7.62) L6(-7.62,-5.08) L7(-7.62,-2.54) L8(-7.62,0) L9(-7.62,2.54) L10(-7.62,5.08) L11(-7.62,7.62) L12(-7.62,10.16) L13(-7.62,12.7) L14(-7.62,15.24) L15(-7.62,17.78) M1(-10.16,-17.78) M2(-10.16,-15.24) M3(-10.16,-12.7) M4(-10.16,-10.16) M5(-10.16,-7.62) M6(-10.16,-5.08) M7(-10.16,-2.54) M8(-10.16,0) M9(-10.16,2.54) M10(-10.16,5.08) M11(-10.16,7.62) M12(-10.16,10.16) M13(-10.16,12.7) M14(-10.16,15.24) M15(-10.16,17.78) N1(-12.7,-17.78) N2(-12.7,-15.24) N3(-12.7,-12.7) N4(-12.7,-10.16) N5(-12.7,-7.62) N6(-12.7,-5.08) N7(-12.7,-2.54) N8(-12.7,0) N9(-12.7,2.54) N10(-12.7,5.08) N11(-12.7,7.62) N12(-12.7,10.16) N13(-12.7,12.7) N14(-12.7,15.24) N15(-12.7,17.78) P1(-15.24,-17.78) P2(-15.24,-15.24) P3(-15.24,-12.7) P4(-15.24,-10.16) P5(-15.24,-7.62) P6(-15.24,-5.08) P7(-15.24,-2.54) P8(-15.24,0) P9(-15.24,2.54) P10(-15.24,5.08) P11(-15.24,7.62) P12(-15.24,10.16) P13(-15.24,12.7) P14(-15.24,15.24) P15(-15.24,17.78) R1(-17.78,-17.78) R2(-17.78,-15.24) R3(-17.78,-12.7) R4(-17.78,-10.16) R5(-17.78,-7.62) R6(-17.78,-5.08) R7(-17.78,-2.54) R8(-17.78,0) R9(-17.78,2.54) R10(-17.78,5.08) R11(-17.78,7.62) R12(-17.78,10.16) R13(-17.78,12.7) R14(-17.78,15.24) R15(-17.78,17.78)
  silkscreen extent -22.27,-26.78 26.55,32.08, body extent -21.72,-26.79 25.91,31.48, height 8.64
FIDRTB50 [mil] "Fiducial Top & Bottom round 50mil"
  round 50 smd paste-100 mask+25: 0(0,0)
  round 50 smd far side paste-100 mask+25: 0(0,0)
  Top Layer - SIG1 keep-out circle w1: c0,0 r50
  Bottom Layer - SIG4 keep-out circle w1: c0,0 r50
LC0402N1R [mm] "Chip inductor 0402 ROUNDED PAD"
  rrect50% 0.6x0.65 smd: 1(-0.55,0) 2(0.55,0)
  silkscreen extent 0,-0.25 0,0.25, body extent -0.51,-0.25 0.51,0.25, height 0.5
LC1008CS [mil] "Chip Inductor, 2-Leads, Body 2,92x2,79mm, IPC Medium Density"
  rrect50% 40x100 smd: 1(-45,0) 2(45,0)
  silkscreen extent -4,-54 4,54, body extent -57,-55 57,55, height 80
MMM1362 [mil]
  rect 20x37 smd: 1(-25.5,-43.5) 3(25.5,43.5) 4(-25.5,43.5)
  rect 31x37 smd: 2(19.5,-43.5)
  body extent -44,-27 45,27, height 44
RC0402N1R [mm] "Chip capacitor 0402 ROUNDED PAD"
  rrect50% 0.6x0.65 smd: 1(-0.55,0) 2(0.55,0)
  silkscreen extent 0,-0.25 0,0.25, body extent -0.51,-0.25 0.51,0.25, height 0.36

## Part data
A1_C1 A1_C13 A1_Cin_1 A2_C1 A2_C13 A2_Cin_1 A3_C1 A3_C13 A3_Cin_1 A4_C1 A4_C13 A4_Cin_1 A5_C1 A5_C13 A5_Cin_1 A6_C1 A6_C13 A6_Cin_1 A7_C1 A7_C13 A7_Cin_1 A8_C1 A8_C13 A8_Cin_1 A9_C1 A9_C13 A9_Cin_1 A10_C1 A10_C13 A10_Cin_1 A11_C1 A11_C13 A11_Cin_1 A12_C1 A12_C13 A12_Cin_1 A13_C1 A13_C13 A13_Cin_1 A14_C1 A14_C13 A14_Cin_1 A15_C1 A15_C13 A15_Cin_1 A16_C1 A16_C13 A16_Cin_1 A17_C1 A17_C13 A17_Cin_1 A18_C1 A18_C13 A18_Cin_1 A19_C1 A19_C13 A19_Cin_1 A20_C1 A20_C13 A20_Cin_1 A21_C1 A21_C13 A21_Cin_1 A22_C1 A22_C13 A22_Cin_1 A23_C1 A23_C13 A23_Cin_1 A24_C1 A24_C13 A24_Cin_1 A25_C1 A25_C13 A25_Cin_1 A26_C1 A26_C13 A26_Cin_1 A27_C1 A27_C13 A27_Cin_1 A28_C1 A28_C13 A28_Cin_1 A29_C1 A29_C13 A29_Cin_1 A30_C1 A30_C13 A30_Cin_1 A31_C1 A31_C13 A31_Cin_1 A32_C1 A32_C13 A32_Cin_1 A33_C1 A33_C13 A33_Cin_1 A34_C1 A34_C13 A34_Cin_1 A35_C1 A35_C13 A35_Cin_1 A36_C1 A36_C13 A36_Cin_1 A37_C1 A37_C13 A37_Cin_1 A38_C1 A38_C13 A38_Cin_1 A39_C1 A39_C13 A39_Cin_1 A40_C1 A40_C13 A40_Cin_1 A41_C1 A41_C13 A41_Cin_1 A42_C1 A42_C13 A42_Cin_1 A43_C1 A43_C13 A43_Cin_1 A44_C1 A44_C13 A44_Cin_1 A45_C1 A45_C13 A45_Cin_1 A46_C1 A46_C13 A46_Cin_1 A47_C1 A47_C13 A47_Cin_1 A48_C1 A48_C13 A48_Cin_1 A49_C1 A49_C13 A49_Cin_1 A50_C1 A50_C13 A50_Cin_1 A51_C1 A51_C13 A51_Cin_1 A52_C1 A52_C13 A52_Cin_1 A53_C1 A53_C13 A53_Cin_1 A54_C1 A54_C13 A54_Cin_1 A55_C1 A55_C13 A55_Cin_1 A56_C1 A56_C13 A56_Cin_1 A57_C1 A57_C13 A57_Cin_1 A58_C1 A58_C13 A58_Cin_1 A59_C1 A59_C13 A59_Cin_1 A60_C1 A60_C13 A60_Cin_1 A61_C1 A61_C13 A61_Cin_1 A62_C1 A62_C13 A62_Cin_1 A63_C1 A63_C13 A63_Cin_1 A64_C1 A64_C13 A64_Cin_1: library part CAPCC0402_1_10.0N_50VX7R, "Capacitor chip ceramic 0402 50V X7R"
A1_C2 A2_C2 A3_C2 A4_C2 A5_C2 A6_C2 A7_C2 A8_C2 A9_C2 A10_C2 A11_C2 A12_C2 A13_C2 A14_C2 A15_C2 A16_C2 A17_C2 A18_C2 A19_C2 A20_C2 A21_C2 A22_C2 A23_C2 A24_C2 A25_C2 A26_C2 A27_C2 A28_C2 A29_C2 A30_C2 A31_C2 A32_C2 A33_C2 A34_C2 A35_C2 A36_C2 A37_C2 A38_C2 A39_C2 A40_C2 A41_C2 A42_C2 A43_C2 A44_C2 A45_C2 A46_C2 A47_C2 A48_C2 A49_C2 A50_C2 A51_C2 A52_C2 A53_C2 A54_C2 A55_C2 A56_C2 A57_C2 A58_C2 A59_C2 A60_C2 A61_C2 A62_C2 A63_C2 A64_C2: library part CAPCC0402_1_100N_50VX7R, "Capacitor chip ceramic 0402 50V X7R"
A1_C3 A2_C3 A3_C3 A4_C3 A5_C3 A6_C3 A7_C3 A8_C3 A9_C3 A10_C3 A11_C3 A12_C3 A13_C3 A14_C3 A15_C3 A16_C3 A17_C3 A18_C3 A19_C3 A20_C3 A21_C3 A22_C3 A23_C3 A24_C3 A25_C3 A26_C3 A27_C3 A28_C3 A29_C3 A30_C3 A31_C3 A32_C3 A33_C3 A34_C3 A35_C3 A36_C3 A37_C3 A38_C3 A39_C3 A40_C3 A41_C3 A42_C3 A43_C3 A44_C3 A45_C3 A46_C3 A47_C3 A48_C3 A49_C3 A50_C3 A51_C3 A52_C3 A53_C3 A54_C3 A55_C3 A56_C3 A57_C3 A58_C3 A59_C3 A60_C3 A61_C3 A62_C3 A63_C3 A64_C3: library part CAPCC0603_2_1U_50VX7R, "Capacitor chip ceramic 0603 50V X7R"
A1_L1 A2_L1 A3_L1 A4_L1 A5_L1 A6_L1 A7_L1 A8_L1 A9_L1 A10_L1 A11_L1 A12_L1 A13_L1 A14_L1 A15_L1 A16_L1 A17_L1 A18_L1 A19_L1 A20_L1 A21_L1 A22_L1 A23_L1 A24_L1 A25_L1 A26_L1 A27_L1 A28_L1 A29_L1 A30_L1 A31_L1 A32_L1 A33_L1 A34_L1 A35_L1 A36_L1 A37_L1 A38_L1 A39_L1 A40_L1 A41_L1 A42_L1 A43_L1 A44_L1 A45_L1 A46_L1 A47_L1 A48_L1 A49_L1 A50_L1 A51_L1 A52_L1 A53_L1 A54_L1 A55_L1 A56_L1 A57_L1 A58_L1 A59_L1 A60_L1 A61_L1 A62_L1 A63_L1 A64_L1: library part IND1008-1.5U_0.33A, "Chip inductor 1008 0.33A 2.3R"
A1_L2 A2_L2 A3_L2 A4_L2 A5_L2 A6_L2 A7_L2 A8_L2 A9_L2 A10_L2 A11_L2 A12_L2 A13_L2 A14_L2 A15_L2 A16_L2 A17_L2 A18_L2 A19_L2 A20_L2 A21_L2 A22_L2 A23_L2 A24_L2 A25_L2 A26_L2 A27_L2 A28_L2 A29_L2 A30_L2 A31_L2 A32_L2 A33_L2 A34_L2 A35_L2 A36_L2 A37_L2 A38_L2 A39_L2 A40_L2 A41_L2 A42_L2 A43_L2 A44_L2 A45_L2 A46_L2 A47_L2 A48_L2 A49_L2 A50_L2 A51_L2 A52_L2 A53_L2 A54_L2 A55_L2 A56_L2 A57_L2 A58_L2 A59_L2 A60_L2 A61_L2 A62_L2 A63_L2 A64_L2: library part IND0402-10.5N_1.0A, "Chip inductor 0402 1.0A 100mR"
A1_RF1 A2_RF1 A3_RF1 A4_RF1 A5_RF1 A6_RF1 A7_RF1 A8_RF1 A9_RF1 A10_RF1 A11_RF1 A12_RF1 A13_RF1 A14_RF1 A15_RF1 A16_RF1 A17_RF1 A18_RF1 A19_RF1 A20_RF1 A21_RF1 A22_RF1 A23_RF1 A24_RF1 A25_RF1 A26_RF1 A27_RF1 A28_RF1 A29_RF1 A30_RF1 A31_RF1 A32_RF1 A33_RF1 A34_RF1 A35_RF1 A36_RF1 A37_RF1 A38_RF1 A39_RF1 A40_RF1 A41_RF1 A42_RF1 A43_RF1 A44_RF1 A45_RF1 A46_RF1 A47_RF1 A48_RF1 A49_RF1 A50_RF1 A51_RF1 A52_RF1 A53_RF1 A54_RF1 A55_RF1 A56_RF1 A57_RF1 A58_RF1 A59_RF1 A60_RF1 A61_RF1 A62_RF1 A63_RF1 A64_RF1: "Monolithic Amplifier 50MHz - 4GHz, 0.75NF"
A1_Rin_1 A2_Rin_1 A3_Rin_1 A4_Rin_1 A5_Rin_1 A6_Rin_1 A7_Rin_1 A8_Rin_1 A9_Rin_1 A10_Rin_1 A11_Rin_1 A12_Rin_1 A13_Rin_1 A14_Rin_1 A15_Rin_1 A16_Rin_1 A17_Rin_1 A18_Rin_1 A19_Rin_1 A20_Rin_1 A21_Rin_1 A22_Rin_1 A23_Rin_1 A24_Rin_1 A25_Rin_1 A26_Rin_1 A27_Rin_1 A28_Rin_1 A29_Rin_1 A30_Rin_1 A31_Rin_1 A32_Rin_1 A33_Rin_1 A34_Rin_1 A35_Rin_1 A36_Rin_1 A37_Rin_1 A38_Rin_1 A39_Rin_1 A40_Rin_1 A41_Rin_1 A42_Rin_1 A43_Rin_1 A44_Rin_1 A45_Rin_1 A46_Rin_1 A47_Rin_1 A48_Rin_1 A49_Rin_1 A50_Rin_1 A51_Rin_1 A52_Rin_1 A53_Rin_1 A54_Rin_1 A55_Rin_1 A56_Rin_1 A57_Rin_1 A58_Rin_1 A59_Rin_1 A60_Rin_1 A61_Rin_1 A62_Rin_1 A63_Rin_1 A64_Rin_1: library part "RES SMD 390 OHM 1% 1/10W 0402", "Chip Resistor 0402 0.1mW 1% 100ppm"
C4 C5 C6 C7 C8 C9 C10 C11 C12 C14 C15 C16 C17 C18 C19 C20: library part CAPCC1206_47U_10VX5R, "Capacitor chip ceramic 1206 10V X5R"
C21 C22 C23 C24 C25 C26 C27 C28: library part CAPT7343_330U_16V, "Capacitor tantal smd 7343-43 16V 50mResr"
C29 C30 C31 C32: library part CAPPS1000U-16V80mR, "Capacitor electrolitic SMD 10x10x8mm 16V 80mR"
CONN1 CONN2 CONN3 CONN4: library part "20 Pin Connector-Samtec-ERF8-010-05.0-L-DV-L-TR", "20 Pin Connector-Samtec-ERF8-010-05.0-L-DV-L-TR"
FID1 FID2 FID3: "Fiducial top & bottom round open mask"
K1: library part CN_Fermionics, "Fermionics Socket PGA15x15"
K2: library part CN_MSTBA2R5.08V, "Combicon header 2 pin vertical closed R5.08mm 12A 300V"

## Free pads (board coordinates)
  round 236.22 hole 129.92: M3(0,196.85) M3(0,2559.06) M3(1670.33,-1473.48) M3(1670.33,4229.39) M3(4032.54,-1473.48) M3(4032.54,4229.39) M3(5702.87,196.85) M3(5702.87,2559.06)

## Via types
v1: diameter 25.59, hole 11.81, Layer 5 - GND2 to Bottom Layer - SIG4, tented both sides, 1069 vias
v2: diameter 25.59, hole 11.81, Top Layer - SIG1 to Layer 2 - GND1, tented both sides, 851 vias
v3: diameter 25.59, hole 11.81, Top Layer - SIG1 to Bottom Layer - SIG4, tented both sides, 384 vias
v4: diameter 29.53, hole 11.81, Top Layer - SIG1 to Bottom Layer - SIG4, tented both sides, 8 vias
v5: diameter 29.53, hole 11.81, Top Layer - SIG1 to Layer 2 - GND1, tented both sides, 4 vias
